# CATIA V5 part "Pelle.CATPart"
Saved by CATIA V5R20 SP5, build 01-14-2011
Part number: Pelle
Bounding box of the stored display mesh (mm): x -502 to -282, y -350 to -250, z -100 to 100
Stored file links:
  U:\CFAO\Thinkmotion\Pelle.CATPart
  U:\CFAO\Thinkmotion\Bras Articule.CATProduct
  U:\CFAO\Thinkmotion\Squelette Pelle.CATPart
  U:\CFAO\Thinkmotion\Bielle 7.CATPart
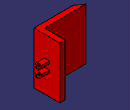
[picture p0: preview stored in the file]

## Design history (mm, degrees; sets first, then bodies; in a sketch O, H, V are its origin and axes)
Set1
  Plane1: linked copy from another document
  Line1: linked copy from another document
  Point1: linked copy from another document
  DatumCurve1: linked copy from another document
  Plane2: linked copy from another document
Body1 (main body)
  Sketch1 on Plane1, origin (0, -300, 0), H (-1, 0, 0), V (0, 0, 1)
    line L1 (282, 20) -> (322, 20)
    line L2 (322, 20) -> (322, 10)
    line L3 (322, 10) -> (282, 10)
    line L4 (282, 10) -> (282, 20)
    point P5 (282, -10)
    line L5 (282, -10) -> (322, -10)
    line L6 (322, -10) -> (322, -20)
    line L7 (322, -20) -> (282, -20)
    line L8 (282, -20) -> (282, -10)
    point P7 (322, -20)
    reference projected line E1 (350, 0) -> (290, 0) from Line1
    reference projected point E2 (350, 0) from Point1
    distance L3 L5 = 20
    length L4 = 10
    length L8 = 10
    length L7 = 40
    distance L2 E2 = 28
    horizontal: L1 H, L3 H, L5 H, L7 H
    vertical: L2 V, L4 V, L6 V, L8 V
    coincidence: P5 L4, P7 L2
    symmetry: L3 L5 E1
  Pad1: profile Sketch1, direction (0, 1, 0), length 10, mirrored extent
  Sketch2 on face of Pad1 from Sketch1.L1, origin (0, 0, 20), H (1, 0, 0), V (0, 1, 0)
    circle A1 centre (-290, -300) radius 5
    reference projected circle E1 centre (-290, -300) radius 5 from edge of DatumCurve1
    coincidence: A1 E1
  Pocket1: profile Sketch2, direction (0, 0, -1), through (limit type 3)
  Fillet1: radius 10, on edge [start face of Pad1 | face of Pad1 from Sketch1.L4]; edge [face of Pad1 from Sketch1.L4 | end face of Pad1]; edge [face of Pad1 from Sketch1.L8 | end face of Pad1]; edge [start face of Pad1 | face of Pad1 from Sketch1.L8]
  Sketch3 on Plane2, origin (0, 0, 0), H (1, 0, 0), V (0, 1, 0)
    line L1 (-342, -250) -> (-322, -250)
    line L2 (-322, -250) -> (-322, -350)
    line L3 (-322, -350) -> (-472, -350)
    line L4 (-472, -350) -> (-502, -330)
    line L5 (-502, -330) -> (-342, -330)
    line L6 (-342, -330) -> (-342, -250)
    reference projected line E1 (-322, -310) -> (-322, -290) from edge [face of Pad1 from Sketch1.L1 | face of Pad1 from Sketch1.L2]
    reference projected line E2 (-322, -310) -> (-322, -290) from edge [face of Pad1 from Sketch1.L1 | face of Pad1 from Sketch1.L2]
    reference projected line E4 (-322, -290) -> (-282, -290) from edge [face of Pad1 from Sketch1.L1 | end face of Pad1]
    length L1 = 20
    length L2 = 100
    length L3 = 150
    length L5 = 160
    distance L5 L3 = 20
    distance E4 L1 = 40
    horizontal: L1 H, L3 H, L5 H
    vertical: L2 V, L6 V
    coincidence: E1 L2
    parallelism: E2 L2
  Pad2: profile Sketch3, direction (0, 0, 1), length 100, mirrored extent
